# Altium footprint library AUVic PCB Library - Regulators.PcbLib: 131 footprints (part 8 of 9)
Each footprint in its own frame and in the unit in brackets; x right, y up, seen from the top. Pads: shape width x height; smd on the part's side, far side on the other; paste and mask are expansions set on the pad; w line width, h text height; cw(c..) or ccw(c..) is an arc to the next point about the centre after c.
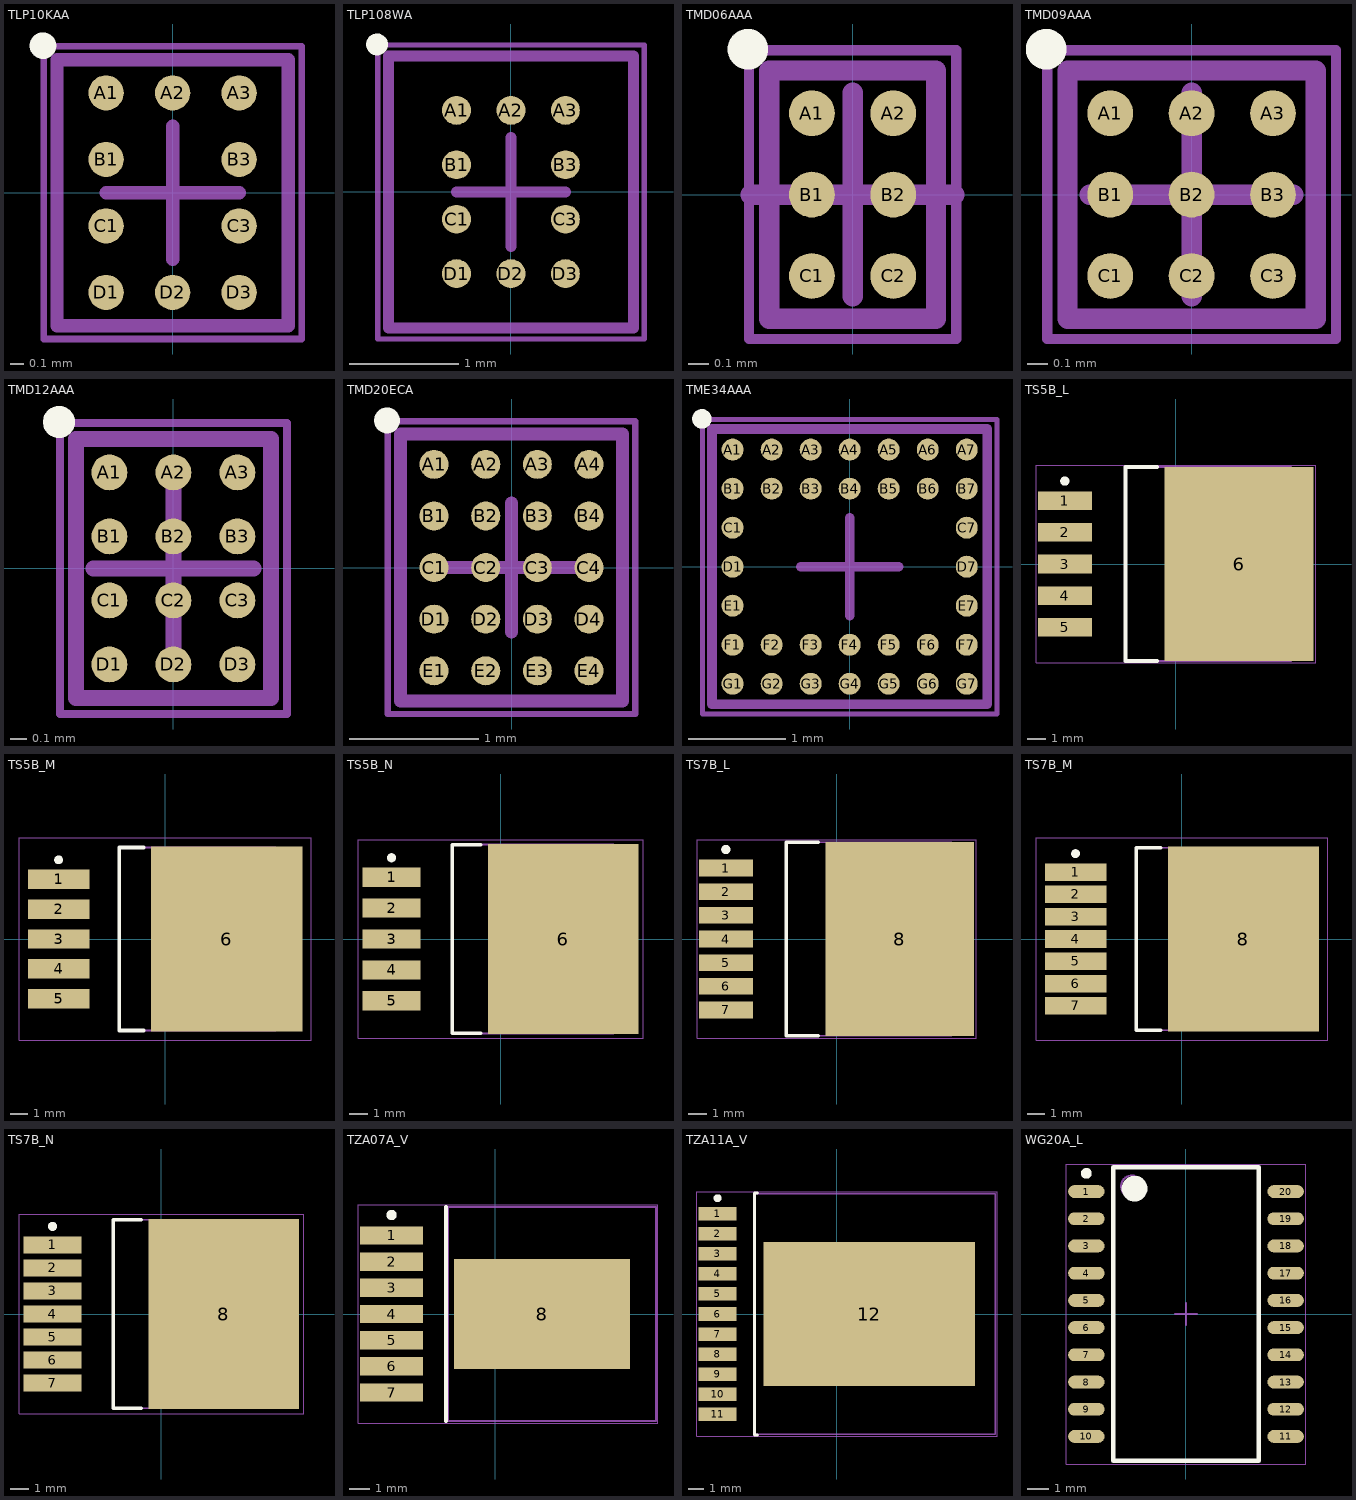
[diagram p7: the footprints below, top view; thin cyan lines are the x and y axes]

## TLP10KAA [mm] "Micro SMD, 10-Leads, Body 2x1.74mm, Pitch 0.5mm, NSC Recommended"
height 0.68
pads (10):
  round 0.265 smd paste-0.132 mask+0.05: A1(-0.5,0.75) A2(0,0.75) A3(0.5,0.75) B1(-0.5,0.25) B3(0.5,0.25) C1(-0.5,-0.25) C3(0.5,-0.25) D1(-0.5,-0.75) D2(0,-0.75) D3(0.5,-0.75)
Top Overlay:
  circle w0.1: c-0.975,1.105 r0.05
Top Paste:
  circle w0.05: c-0.575,0.675 r0.025
  circle w0.05: c-0.425,0.825 r0.025
  circle w0.05: c-0.425,0.675 r0.025
  circle w0.05: c-0.575,0.825 r0.025
  circle w0.05: c-0.075,0.675 r0.025
  circle w0.05: c0.075,0.825 r0.025
  circle w0.05: c0.075,0.675 r0.025
  circle w0.05: c-0.075,0.825 r0.025
  circle w0.05: c0.425,0.675 r0.025
  circle w0.05: c0.575,0.825 r0.025
  circle w0.05: c0.575,0.675 r0.025
  circle w0.05: c0.425,0.825 r0.025
  circle w0.05: c-0.575,0.175 r0.025
  circle w0.05: c-0.425,0.325 r0.025
  circle w0.05: c-0.425,0.175 r0.025
  circle w0.05: c-0.575,0.325 r0.025
  circle w0.05: c0.425,0.175 r0.025
  circle w0.05: c0.575,0.325 r0.025
  circle w0.05: c0.575,0.175 r0.025
  circle w0.05: c0.425,0.325 r0.025
  circle w0.05: c-0.575,-0.325 r0.025
  circle w0.05: c-0.425,-0.175 r0.025
  circle w0.05: c-0.425,-0.325 r0.025
  circle w0.05: c-0.575,-0.175 r0.025
  circle w0.05: c0.425,-0.325 r0.025
  circle w0.05: c0.575,-0.175 r0.025
  circle w0.05: c0.575,-0.325 r0.025
  circle w0.05: c0.425,-0.175 r0.025
  circle w0.05: c-0.575,-0.825 r0.025
  circle w0.05: c-0.425,-0.675 r0.025
  circle w0.05: c-0.425,-0.825 r0.025
  circle w0.05: c-0.575,-0.675 r0.025
  circle w0.05: c-0.075,-0.825 r0.025
  circle w0.05: c0.075,-0.675 r0.025
  circle w0.05: c0.075,-0.825 r0.025
  circle w0.05: c-0.075,-0.675 r0.025
  circle w0.05: c0.425,-0.825 r0.025
  circle w0.05: c0.575,-0.675 r0.025
  circle w0.05: c0.575,-0.825 r0.025
  circle w0.05: c0.425,-0.675 r0.025
  region: -0.575,0.825 -0.575,0.675 -0.425,0.675 -0.425,0.825
  region: -0.575,0.675 -0.575,0.825 -0.625,0.825 -0.625,0.675
  rectangle: -0.575,0.825 -0.425,0.875
  region: -0.425,0.825 -0.425,0.675 -0.375,0.675 -0.375,0.825
  region: -0.425,0.675 -0.575,0.675 -0.575,0.625 -0.425,0.625
  region: -0.075,0.825 -0.075,0.675 0.075,0.675 0.075,0.825
  region: -0.075,0.675 -0.075,0.825 -0.125,0.825 -0.125,0.675
  rectangle: -0.075,0.825 0.075,0.875
  region: 0.075,0.825 0.075,0.675 0.125,0.675 0.125,0.825
  region: 0.075,0.675 -0.075,0.675 -0.075,0.625 0.075,0.625
  region: 0.425,0.825 0.425,0.675 0.575,0.675 0.575,0.825
  region: 0.425,0.675 0.425,0.825 0.375,0.825 0.375,0.675
  rectangle: 0.425,0.825 0.575,0.875
  region: 0.575,0.825 0.575,0.675 0.625,0.675 0.625,0.825
  region: 0.575,0.675 0.425,0.675 0.425,0.625 0.575,0.625
  region: -0.575,0.325 -0.575,0.175 -0.425,0.175 -0.425,0.325
  region: -0.575,0.175 -0.575,0.325 -0.625,0.325 -0.625,0.175
  rectangle: -0.575,0.325 -0.425,0.375
  region: -0.425,0.325 -0.425,0.175 -0.375,0.175 -0.375,0.325
  region: -0.425,0.175 -0.575,0.175 -0.575,0.125 -0.425,0.125
  region: 0.425,0.325 0.425,0.175 0.575,0.175 0.575,0.325
  region: 0.425,0.175 0.425,0.325 0.375,0.325 0.375,0.175
  rectangle: 0.425,0.325 0.575,0.375
  region: 0.575,0.325 0.575,0.175 0.625,0.175 0.625,0.325
  region: 0.575,0.175 0.425,0.175 0.425,0.125 0.575,0.125
  region: -0.575,-0.175 -0.575,-0.325 -0.425,-0.325 -0.425,-0.175
  region: -0.575,-0.325 -0.575,-0.175 -0.625,-0.175 -0.625,-0.325
  rectangle: -0.575,-0.175 -0.425,-0.125
  region: -0.425,-0.175 -0.425,-0.325 -0.375,-0.325 -0.375,-0.175
  region: -0.425,-0.325 -0.575,-0.325 -0.575,-0.375 -0.425,-0.375
  region: 0.425,-0.175 0.425,-0.325 0.575,-0.325 0.575,-0.175
  region: 0.425,-0.325 0.425,-0.175 0.375,-0.175 0.375,-0.325
  rectangle: 0.425,-0.175 0.575,-0.125
  region: 0.575,-0.175 0.575,-0.325 0.625,-0.325 0.625,-0.175
  region: 0.575,-0.325 0.425,-0.325 0.425,-0.375 0.575,-0.375
  region: -0.575,-0.675 -0.575,-0.825 -0.425,-0.825 -0.425,-0.675
  region: -0.575,-0.825 -0.575,-0.675 -0.625,-0.675 -0.625,-0.825
  rectangle: -0.575,-0.675 -0.425,-0.625
  region: -0.425,-0.675 -0.425,-0.825 -0.375,-0.825 -0.375,-0.675
  region: -0.425,-0.825 -0.575,-0.825 -0.575,-0.875 -0.425,-0.875
  region: -0.075,-0.675 -0.075,-0.825 0.075,-0.825 0.075,-0.675
  region: -0.075,-0.825 -0.075,-0.675 -0.125,-0.675 -0.125,-0.825
  rectangle: -0.075,-0.675 0.075,-0.625
  region: 0.075,-0.675 0.075,-0.825 0.125,-0.825 0.125,-0.675
  region: 0.075,-0.825 -0.075,-0.825 -0.075,-0.875 0.075,-0.875
  region: 0.425,-0.675 0.425,-0.825 0.575,-0.825 0.575,-0.675
  region: 0.425,-0.825 0.425,-0.675 0.375,-0.675 0.375,-0.825
  rectangle: 0.425,-0.675 0.575,-0.625
  region: 0.575,-0.675 0.575,-0.825 0.625,-0.825 0.625,-0.675
  region: 0.575,-0.825 0.425,-0.825 0.425,-0.875 0.575,-0.875
Mechanical 13:
  lines w0.1: -0.87,-1 -0.87,1 0.87,1 0.87,-1 -0.87,-1
Mechanical 15:
  lines w0.05: -0.97,-1.1 -0.97,1.1 0.97,1.1 0.97,-1.1 -0.97,-1.1
  lines w0.1: -0.5,0 0.5,0 ; 0,-0.5 0,0.5
3D body: height 0.68, standoff 0, extent -0.87,-1 0.87,1

## TLP108WA [mm] "Micro SMD, 10-Leads, Body 2.5x2.25mm, Pitch 0.5mm, NSC Recommended"
height 0.68
pads (10):
  round 0.265 smd paste-0.132 mask+0.05: A1(-0.5,0.75) A2(0,0.75) A3(0.5,0.75) B1(-0.5,0.25) B3(0.5,0.25) C1(-0.5,-0.25) C3(0.5,-0.25) D1(-0.5,-0.75) D2(0,-0.75) D3(0.5,-0.75)
Top Overlay:
  circle w0.1: c-1.23,1.355 r0.05
Top Paste:
  circle w0.05: c-0.575,0.675 r0.025
  circle w0.05: c-0.425,0.825 r0.025
  circle w0.05: c-0.425,0.675 r0.025
  circle w0.05: c-0.575,0.825 r0.025
  circle w0.05: c-0.075,0.675 r0.025
  circle w0.05: c0.075,0.825 r0.025
  circle w0.05: c0.075,0.675 r0.025
  circle w0.05: c-0.075,0.825 r0.025
  circle w0.05: c0.425,0.675 r0.025
  circle w0.05: c0.575,0.825 r0.025
  circle w0.05: c0.575,0.675 r0.025
  circle w0.05: c0.425,0.825 r0.025
  circle w0.05: c-0.575,0.175 r0.025
  circle w0.05: c-0.425,0.325 r0.025
  circle w0.05: c-0.425,0.175 r0.025
  circle w0.05: c-0.575,0.325 r0.025
  circle w0.05: c0.425,0.175 r0.025
  circle w0.05: c0.575,0.325 r0.025
  circle w0.05: c0.575,0.175 r0.025
  circle w0.05: c0.425,0.325 r0.025
  circle w0.05: c-0.575,-0.325 r0.025
  circle w0.05: c-0.425,-0.175 r0.025
  circle w0.05: c-0.425,-0.325 r0.025
  circle w0.05: c-0.575,-0.175 r0.025
  circle w0.05: c0.425,-0.325 r0.025
  circle w0.05: c0.575,-0.175 r0.025
  circle w0.05: c0.575,-0.325 r0.025
  circle w0.05: c0.425,-0.175 r0.025
  circle w0.05: c-0.575,-0.825 r0.025
  circle w0.05: c-0.425,-0.675 r0.025
  circle w0.05: c-0.425,-0.825 r0.025
  circle w0.05: c-0.575,-0.675 r0.025
  circle w0.05: c-0.075,-0.825 r0.025
  circle w0.05: c0.075,-0.675 r0.025
  circle w0.05: c0.075,-0.825 r0.025
  circle w0.05: c-0.075,-0.675 r0.025
  circle w0.05: c0.425,-0.825 r0.025
  circle w0.05: c0.575,-0.675 r0.025
  circle w0.05: c0.575,-0.825 r0.025
  circle w0.05: c0.425,-0.675 r0.025
  region: -0.575,0.825 -0.575,0.675 -0.425,0.675 -0.425,0.825
  region: -0.575,0.675 -0.575,0.825 -0.625,0.825 -0.625,0.675
  rectangle: -0.575,0.825 -0.425,0.875
  region: -0.425,0.825 -0.425,0.675 -0.375,0.675 -0.375,0.825
  region: -0.425,0.675 -0.575,0.675 -0.575,0.625 -0.425,0.625
  region: -0.075,0.825 -0.075,0.675 0.075,0.675 0.075,0.825
  region: -0.075,0.675 -0.075,0.825 -0.125,0.825 -0.125,0.675
  rectangle: -0.075,0.825 0.075,0.875
  region: 0.075,0.825 0.075,0.675 0.125,0.675 0.125,0.825
  region: 0.075,0.675 -0.075,0.675 -0.075,0.625 0.075,0.625
  region: 0.425,0.825 0.425,0.675 0.575,0.675 0.575,0.825
  region: 0.425,0.675 0.425,0.825 0.375,0.825 0.375,0.675
  rectangle: 0.425,0.825 0.575,0.875
  region: 0.575,0.825 0.575,0.675 0.625,0.675 0.625,0.825
  region: 0.575,0.675 0.425,0.675 0.425,0.625 0.575,0.625
  region: -0.575,0.325 -0.575,0.175 -0.425,0.175 -0.425,0.325
  region: -0.575,0.175 -0.575,0.325 -0.625,0.325 -0.625,0.175
  rectangle: -0.575,0.325 -0.425,0.375
  region: -0.425,0.325 -0.425,0.175 -0.375,0.175 -0.375,0.325
  region: -0.425,0.175 -0.575,0.175 -0.575,0.125 -0.425,0.125
  region: 0.425,0.325 0.425,0.175 0.575,0.175 0.575,0.325
  region: 0.425,0.175 0.425,0.325 0.375,0.325 0.375,0.175
  rectangle: 0.425,0.325 0.575,0.375
  region: 0.575,0.325 0.575,0.175 0.625,0.175 0.625,0.325
  region: 0.575,0.175 0.425,0.175 0.425,0.125 0.575,0.125
  region: -0.575,-0.175 -0.575,-0.325 -0.425,-0.325 -0.425,-0.175
  region: -0.575,-0.325 -0.575,-0.175 -0.625,-0.175 -0.625,-0.325
  rectangle: -0.575,-0.175 -0.425,-0.125
  region: -0.425,-0.175 -0.425,-0.325 -0.375,-0.325 -0.375,-0.175
  region: -0.425,-0.325 -0.575,-0.325 -0.575,-0.375 -0.425,-0.375
  region: 0.425,-0.175 0.425,-0.325 0.575,-0.325 0.575,-0.175
  region: 0.425,-0.325 0.425,-0.175 0.375,-0.175 0.375,-0.325
  rectangle: 0.425,-0.175 0.575,-0.125
  region: 0.575,-0.175 0.575,-0.325 0.625,-0.325 0.625,-0.175
  region: 0.575,-0.325 0.425,-0.325 0.425,-0.375 0.575,-0.375
  region: -0.575,-0.675 -0.575,-0.825 -0.425,-0.825 -0.425,-0.675
  region: -0.575,-0.825 -0.575,-0.675 -0.625,-0.675 -0.625,-0.825
  rectangle: -0.575,-0.675 -0.425,-0.625
  region: -0.425,-0.675 -0.425,-0.825 -0.375,-0.825 -0.375,-0.675
  region: -0.425,-0.825 -0.575,-0.825 -0.575,-0.875 -0.425,-0.875
  region: -0.075,-0.675 -0.075,-0.825 0.075,-0.825 0.075,-0.675
  region: -0.075,-0.825 -0.075,-0.675 -0.125,-0.675 -0.125,-0.825
  rectangle: -0.075,-0.675 0.075,-0.625
  region: 0.075,-0.675 0.075,-0.825 0.125,-0.825 0.125,-0.675
  region: 0.075,-0.825 -0.075,-0.825 -0.075,-0.875 0.075,-0.875
  region: 0.425,-0.675 0.425,-0.825 0.575,-0.825 0.575,-0.675
  region: 0.425,-0.825 0.425,-0.675 0.375,-0.675 0.375,-0.825
  rectangle: 0.425,-0.675 0.575,-0.625
  region: 0.575,-0.675 0.575,-0.825 0.625,-0.825 0.625,-0.675
  region: 0.575,-0.825 0.425,-0.825 0.425,-0.875 0.575,-0.875
Mechanical 13:
  lines w0.1: -1.125,-1.25 -1.125,1.25 1.125,1.25 1.125,-1.25 -1.125,-1.25
Mechanical 15:
  lines w0.05: -1.225,-1.35 -1.225,1.35 1.225,1.35 1.225,-1.35 -1.225,-1.35
  lines w0.1: -0.5,0 0.5,0 ; 0,-0.5 0,0.5
3D body: height 0.68, standoff 0, extent -1.125,-1.25 1.125,1.25

## TMD06AAA [mm] "Micro SMD, 6-Leads, Body 1.22x0.82mm, Pitch 0.4mm, NSC Recommended"
height 0.68
pads (6):
  round 0.225 smd paste-0.112 mask+0.05: A1(-0.2,0.4) A2(0.2,0.4) B1(-0.2,0) B2(0.2,0) C1(-0.2,-0.4) C2(0.2,-0.4)
Top Overlay:
  circle w0.1: c-0.515,0.715 r0.05
Top Paste:
  circle w0.05: c0.275,-0.475 r0.025
  circle w0.05: c0.125,-0.325 r0.025
  circle w0.05: c0.125,-0.475 r0.025
  circle w0.05: c0.275,-0.325 r0.025
  circle w0.05: c-0.125,-0.475 r0.025
  circle w0.05: c-0.275,-0.325 r0.025
  circle w0.05: c-0.275,-0.475 r0.025
  circle w0.05: c-0.125,-0.325 r0.025
  circle w0.05: c0.275,-0.075 r0.025
  circle w0.05: c0.125,0.075 r0.025
  circle w0.05: c0.125,-0.075 r0.025
  circle w0.05: c0.275,0.075 r0.025
  circle w0.05: c-0.125,-0.075 r0.025
  circle w0.05: c-0.275,0.075 r0.025
  circle w0.05: c-0.275,-0.075 r0.025
  circle w0.05: c-0.125,0.075 r0.025
  circle w0.05: c0.275,0.325 r0.025
  circle w0.05: c0.125,0.475 r0.025
  circle w0.05: c0.125,0.325 r0.025
  circle w0.05: c0.275,0.475 r0.025
  circle w0.05: c-0.125,0.325 r0.025
  circle w0.05: c-0.275,0.475 r0.025
  circle w0.05: c-0.275,0.325 r0.025
  circle w0.05: c-0.125,0.475 r0.025
  region: 0.125,-0.325 0.125,-0.475 0.275,-0.475 0.275,-0.325
  region: 0.325,-0.475 0.325,-0.325 0.275,-0.325 0.275,-0.475
  region: 0.275,-0.275 0.125,-0.275 0.125,-0.325 0.275,-0.325
  region: 0.075,-0.325 0.075,-0.475 0.125,-0.475 0.125,-0.325
  rectangle: 0.125,-0.525 0.275,-0.475
  region: -0.275,-0.325 -0.275,-0.475 -0.125,-0.475 -0.125,-0.325
  region: -0.075,-0.475 -0.075,-0.325 -0.125,-0.325 -0.125,-0.475
  region: -0.125,-0.275 -0.275,-0.275 -0.275,-0.325 -0.125,-0.325
  region: -0.325,-0.325 -0.325,-0.475 -0.275,-0.475 -0.275,-0.325
  rectangle: -0.275,-0.525 -0.125,-0.475
  region: 0.125,0.075 0.125,-0.075 0.275,-0.075 0.275,0.075
  region: 0.325,-0.075 0.325,0.075 0.275,0.075 0.275,-0.075
  region: 0.275,0.125 0.125,0.125 0.125,0.075 0.275,0.075
  region: 0.075,0.075 0.075,-0.075 0.125,-0.075 0.125,0.075
  rectangle: 0.125,-0.125 0.275,-0.075
  region: -0.275,0.075 -0.275,-0.075 -0.125,-0.075 -0.125,0.075
  region: -0.075,-0.075 -0.075,0.075 -0.125,0.075 -0.125,-0.075
  region: -0.125,0.125 -0.275,0.125 -0.275,0.075 -0.125,0.075
  region: -0.325,0.075 -0.325,-0.075 -0.275,-0.075 -0.275,0.075
  rectangle: -0.275,-0.125 -0.125,-0.075
  region: 0.125,0.475 0.125,0.325 0.275,0.325 0.275,0.475
  region: 0.325,0.325 0.325,0.475 0.275,0.475 0.275,0.325
  region: 0.275,0.525 0.125,0.525 0.125,0.475 0.275,0.475
  region: 0.075,0.475 0.075,0.325 0.125,0.325 0.125,0.475
  rectangle: 0.125,0.275 0.275,0.325
  region: -0.275,0.475 -0.275,0.325 -0.125,0.325 -0.125,0.475
  region: -0.075,0.325 -0.075,0.475 -0.125,0.475 -0.125,0.325
  region: -0.125,0.525 -0.275,0.525 -0.275,0.475 -0.125,0.475
  region: -0.325,0.475 -0.325,0.325 -0.275,0.325 -0.275,0.475
  rectangle: -0.275,0.275 -0.125,0.325
Mechanical 13:
  lines w0.1: -0.41,-0.61 0.41,-0.61 0.41,0.61 -0.41,0.61 -0.41,-0.61
Mechanical 15:
  lines w0.05: -0.51,-0.71 0.51,-0.71 0.51,0.71 -0.51,0.71 -0.51,-0.71
  lines w0.1: -0.5,0 0.5,0 ; 0,-0.5 0,0.5
3D body: height 0.68, standoff 0, extent -0.41,-0.61 0.41,0.61

## TMD09AAA [mm] "Micro SMD, 9-Leads, Body 1.22x1.22mm, Pitch 0.4mm, NSC Recommended"
height 0.68
pads (9):
  round 0.225 smd paste-0.112 mask+0.05: A1(-0.4,0.4) A2(0,0.4) A3(0.4,0.4) B1(-0.4,0) B2(0,0) B3(0.4,0) C1(-0.4,-0.4) C2(0,-0.4) C3(0.4,-0.4)
Top Overlay:
  circle w0.1: c-0.715,0.715 r0.05
Top Paste:
  circle w0.05: c0.475,-0.475 r0.025
  circle w0.05: c0.325,-0.325 r0.025
  circle w0.05: c0.325,-0.475 r0.025
  circle w0.05: c0.475,-0.325 r0.025
  circle w0.05: c0.075,-0.475 r0.025
  circle w0.05: c-0.075,-0.325 r0.025
  circle w0.05: c-0.075,-0.475 r0.025
  circle w0.05: c0.075,-0.325 r0.025
  circle w0.05: c-0.325,-0.475 r0.025
  circle w0.05: c-0.475,-0.325 r0.025
  circle w0.05: c-0.475,-0.475 r0.025
  circle w0.05: c-0.325,-0.325 r0.025
  circle w0.05: c0.475,-0.075 r0.025
  circle w0.05: c0.325,0.075 r0.025
  circle w0.05: c0.325,-0.075 r0.025
  circle w0.05: c0.475,0.075 r0.025
  circle w0.05: c0.075,-0.075 r0.025
  circle w0.05: c-0.075,0.075 r0.025
  circle w0.05: c-0.075,-0.075 r0.025
  circle w0.05: c0.075,0.075 r0.025
  circle w0.05: c-0.325,-0.075 r0.025
  circle w0.05: c-0.475,0.075 r0.025
  circle w0.05: c-0.475,-0.075 r0.025
  circle w0.05: c-0.325,0.075 r0.025
  circle w0.05: c0.475,0.325 r0.025
  circle w0.05: c0.325,0.475 r0.025
  circle w0.05: c0.325,0.325 r0.025
  circle w0.05: c0.475,0.475 r0.025
  circle w0.05: c0.075,0.325 r0.025
  circle w0.05: c-0.075,0.475 r0.025
  circle w0.05: c-0.075,0.325 r0.025
  circle w0.05: c0.075,0.475 r0.025
  circle w0.05: c-0.325,0.325 r0.025
  circle w0.05: c-0.475,0.475 r0.025
  circle w0.05: c-0.475,0.325 r0.025
  circle w0.05: c-0.325,0.475 r0.025
  region: 0.325,-0.325 0.325,-0.475 0.475,-0.475 0.475,-0.325
  region: 0.525,-0.475 0.525,-0.325 0.475,-0.325 0.475,-0.475
  region: 0.475,-0.275 0.325,-0.275 0.325,-0.325 0.475,-0.325
  region: 0.275,-0.325 0.275,-0.475 0.325,-0.475 0.325,-0.325
  rectangle: 0.325,-0.525 0.475,-0.475
  region: -0.075,-0.325 -0.075,-0.475 0.075,-0.475 0.075,-0.325
  region: 0.125,-0.475 0.125,-0.325 0.075,-0.325 0.075,-0.475
  region: 0.075,-0.275 -0.075,-0.275 -0.075,-0.325 0.075,-0.325
  region: -0.125,-0.325 -0.125,-0.475 -0.075,-0.475 -0.075,-0.325
  rectangle: -0.075,-0.525 0.075,-0.475
  region: -0.475,-0.325 -0.475,-0.475 -0.325,-0.475 -0.325,-0.325
  region: -0.275,-0.475 -0.275,-0.325 -0.325,-0.325 -0.325,-0.475
  region: -0.325,-0.275 -0.475,-0.275 -0.475,-0.325 -0.325,-0.325
  region: -0.525,-0.325 -0.525,-0.475 -0.475,-0.475 -0.475,-0.325
  rectangle: -0.475,-0.525 -0.325,-0.475
  region: 0.325,0.075 0.325,-0.075 0.475,-0.075 0.475,0.075
  region: 0.525,-0.075 0.525,0.075 0.475,0.075 0.475,-0.075
  region: 0.475,0.125 0.325,0.125 0.325,0.075 0.475,0.075
  region: 0.275,0.075 0.275,-0.075 0.325,-0.075 0.325,0.075
  rectangle: 0.325,-0.125 0.475,-0.075
  region: -0.075,0.075 -0.075,-0.075 0.075,-0.075 0.075,0.075
  region: 0.125,-0.075 0.125,0.075 0.075,0.075 0.075,-0.075
  region: 0.075,0.125 -0.075,0.125 -0.075,0.075 0.075,0.075
  region: -0.125,0.075 -0.125,-0.075 -0.075,-0.075 -0.075,0.075
  rectangle: -0.075,-0.125 0.075,-0.075
  region: -0.475,0.075 -0.475,-0.075 -0.325,-0.075 -0.325,0.075
  region: -0.275,-0.075 -0.275,0.075 -0.325,0.075 -0.325,-0.075
  region: -0.325,0.125 -0.475,0.125 -0.475,0.075 -0.325,0.075
  region: -0.525,0.075 -0.525,-0.075 -0.475,-0.075 -0.475,0.075
  rectangle: -0.475,-0.125 -0.325,-0.075
  region: 0.325,0.475 0.325,0.325 0.475,0.325 0.475,0.475
  region: 0.525,0.325 0.525,0.475 0.475,0.475 0.475,0.325
  region: 0.475,0.525 0.325,0.525 0.325,0.475 0.475,0.475
  region: 0.275,0.475 0.275,0.325 0.325,0.325 0.325,0.475
  rectangle: 0.325,0.275 0.475,0.325
  region: -0.075,0.475 -0.075,0.325 0.075,0.325 0.075,0.475
  region: 0.125,0.325 0.125,0.475 0.075,0.475 0.075,0.325
  region: 0.075,0.525 -0.075,0.525 -0.075,0.475 0.075,0.475
  region: -0.125,0.475 -0.125,0.325 -0.075,0.325 -0.075,0.475
  rectangle: -0.075,0.275 0.075,0.325
  region: -0.475,0.475 -0.475,0.325 -0.325,0.325 -0.325,0.475
  region: -0.275,0.325 -0.275,0.475 -0.325,0.475 -0.325,0.325
  region: -0.325,0.525 -0.475,0.525 -0.475,0.475 -0.325,0.475
  region: -0.525,0.475 -0.525,0.325 -0.475,0.325 -0.475,0.475
  rectangle: -0.475,0.275 -0.325,0.325
Mechanical 13:
  lines w0.1: -0.61,-0.61 0.61,-0.61 0.61,0.61 -0.61,0.61 -0.61,-0.61
Mechanical 15:
  lines w0.05: -0.71,-0.71 0.71,-0.71 0.71,0.71 -0.71,0.71 -0.71,-0.71
  lines w0.1: -0.5,0 0.5,0 ; 0,-0.5 0,0.5
3D body: height 0.68, standoff 0, extent -0.61,-0.61 0.61,0.61

## TMD12AAA [mm] "Micro SMD, 12-Leads, Body 1.62x1.22mm, Pitch 0.4mm, NSC Recommended"
height 0.68
pads (12):
  round 0.225 smd paste-0.112 mask+0.05: A1(-0.4,0.6) A2(0,0.6) A3(0.4,0.6) B1(-0.4,0.2) B2(0,0.2) B3(0.4,0.2) C1(-0.4,-0.2) C2(0,-0.2) C3(0.4,-0.2) D1(-0.4,-0.6) D2(0,-0.6) D3(0.4,-0.6)
Top Overlay:
  circle w0.1: c-0.715,0.915 r0.05
Top Paste:
  circle w0.05: c0.475,-0.675 r0.025
  circle w0.05: c0.325,-0.525 r0.025
  circle w0.05: c0.325,-0.675 r0.025
  circle w0.05: c0.475,-0.525 r0.025
  circle w0.05: c0.075,-0.675 r0.025
  circle w0.05: c-0.075,-0.525 r0.025
  circle w0.05: c-0.075,-0.675 r0.025
  circle w0.05: c0.075,-0.525 r0.025
  circle w0.05: c-0.325,-0.675 r0.025
  circle w0.05: c-0.475,-0.525 r0.025
  circle w0.05: c-0.475,-0.675 r0.025
  circle w0.05: c-0.325,-0.525 r0.025
  circle w0.05: c0.475,-0.275 r0.025
  circle w0.05: c0.325,-0.125 r0.025
  circle w0.05: c0.325,-0.275 r0.025
  circle w0.05: c0.475,-0.125 r0.025
  circle w0.05: c0.075,-0.275 r0.025
  circle w0.05: c-0.075,-0.125 r0.025
  circle w0.05: c-0.075,-0.275 r0.025
  circle w0.05: c0.075,-0.125 r0.025
  circle w0.05: c-0.325,-0.275 r0.025
  circle w0.05: c-0.475,-0.125 r0.025
  circle w0.05: c-0.475,-0.275 r0.025
  circle w0.05: c-0.325,-0.125 r0.025
  circle w0.05: c0.475,0.125 r0.025
  circle w0.05: c0.325,0.275 r0.025
  circle w0.05: c0.325,0.125 r0.025
  circle w0.05: c0.475,0.275 r0.025
  circle w0.05: c0.075,0.125 r0.025
  circle w0.05: c-0.075,0.275 r0.025
  circle w0.05: c-0.075,0.125 r0.025
  circle w0.05: c0.075,0.275 r0.025
  circle w0.05: c-0.325,0.125 r0.025
  circle w0.05: c-0.475,0.275 r0.025
  circle w0.05: c-0.475,0.125 r0.025
  circle w0.05: c-0.325,0.275 r0.025
  circle w0.05: c0.475,0.525 r0.025
  circle w0.05: c0.325,0.675 r0.025
  circle w0.05: c0.325,0.525 r0.025
  circle w0.05: c0.475,0.675 r0.025
  circle w0.05: c0.075,0.525 r0.025
  circle w0.05: c-0.075,0.675 r0.025
  circle w0.05: c-0.075,0.525 r0.025
  circle w0.05: c0.075,0.675 r0.025
  circle w0.05: c-0.325,0.525 r0.025
  circle w0.05: c-0.475,0.675 r0.025
  circle w0.05: c-0.475,0.525 r0.025
  circle w0.05: c-0.325,0.675 r0.025
  region: 0.325,-0.525 0.325,-0.675 0.475,-0.675 0.475,-0.525
  region: 0.525,-0.675 0.525,-0.525 0.475,-0.525 0.475,-0.675
  region: 0.475,-0.475 0.325,-0.475 0.325,-0.525 0.475,-0.525
  region: 0.275,-0.525 0.275,-0.675 0.325,-0.675 0.325,-0.525
  rectangle: 0.325,-0.725 0.475,-0.675
  region: -0.075,-0.525 -0.075,-0.675 0.075,-0.675 0.075,-0.525
  region: 0.125,-0.675 0.125,-0.525 0.075,-0.525 0.075,-0.675
  region: 0.075,-0.475 -0.075,-0.475 -0.075,-0.525 0.075,-0.525
  region: -0.125,-0.525 -0.125,-0.675 -0.075,-0.675 -0.075,-0.525
  rectangle: -0.075,-0.725 0.075,-0.675
  region: -0.475,-0.525 -0.475,-0.675 -0.325,-0.675 -0.325,-0.525
  region: -0.275,-0.675 -0.275,-0.525 -0.325,-0.525 -0.325,-0.675
  region: -0.325,-0.475 -0.475,-0.475 -0.475,-0.525 -0.325,-0.525
  region: -0.525,-0.525 -0.525,-0.675 -0.475,-0.675 -0.475,-0.525
  rectangle: -0.475,-0.725 -0.325,-0.675
  region: 0.325,-0.125 0.325,-0.275 0.475,-0.275 0.475,-0.125
  region: 0.525,-0.275 0.525,-0.125 0.475,-0.125 0.475,-0.275
  region: 0.475,-0.075 0.325,-0.075 0.325,-0.125 0.475,-0.125
  region: 0.275,-0.125 0.275,-0.275 0.325,-0.275 0.325,-0.125
  rectangle: 0.325,-0.325 0.475,-0.275
  region: -0.075,-0.125 -0.075,-0.275 0.075,-0.275 0.075,-0.125
  region: 0.125,-0.275 0.125,-0.125 0.075,-0.125 0.075,-0.275
  region: 0.075,-0.075 -0.075,-0.075 -0.075,-0.125 0.075,-0.125
  region: -0.125,-0.125 -0.125,-0.275 -0.075,-0.275 -0.075,-0.125
  rectangle: -0.075,-0.325 0.075,-0.275
  region: -0.475,-0.125 -0.475,-0.275 -0.325,-0.275 -0.325,-0.125
  region: -0.275,-0.275 -0.275,-0.125 -0.325,-0.125 -0.325,-0.275
  region: -0.325,-0.075 -0.475,-0.075 -0.475,-0.125 -0.325,-0.125
  region: -0.525,-0.125 -0.525,-0.275 -0.475,-0.275 -0.475,-0.125
  rectangle: -0.475,-0.325 -0.325,-0.275
  region: 0.325,0.275 0.325,0.125 0.475,0.125 0.475,0.275
  region: 0.525,0.125 0.525,0.275 0.475,0.275 0.475,0.125
  region: 0.475,0.325 0.325,0.325 0.325,0.275 0.475,0.275
  region: 0.275,0.275 0.275,0.125 0.325,0.125 0.325,0.275
  rectangle: 0.325,0.075 0.475,0.125
  region: -0.075,0.275 -0.075,0.125 0.075,0.125 0.075,0.275
  region: 0.125,0.125 0.125,0.275 0.075,0.275 0.075,0.125
  region: 0.075,0.325 -0.075,0.325 -0.075,0.275 0.075,0.275
  region: -0.125,0.275 -0.125,0.125 -0.075,0.125 -0.075,0.275
  rectangle: -0.075,0.075 0.075,0.125
  region: -0.475,0.275 -0.475,0.125 -0.325,0.125 -0.325,0.275
  region: -0.275,0.125 -0.275,0.275 -0.325,0.275 -0.325,0.125
  region: -0.325,0.325 -0.475,0.325 -0.475,0.275 -0.325,0.275
  region: -0.525,0.275 -0.525,0.125 -0.475,0.125 -0.475,0.275
  rectangle: -0.475,0.075 -0.325,0.125
  region: 0.325,0.675 0.325,0.525 0.475,0.525 0.475,0.675
  region: 0.525,0.525 0.525,0.675 0.475,0.675 0.475,0.525
  region: 0.475,0.725 0.325,0.725 0.325,0.675 0.475,0.675
  region: 0.275,0.675 0.275,0.525 0.325,0.525 0.325,0.675
  rectangle: 0.325,0.475 0.475,0.525
  region: -0.075,0.675 -0.075,0.525 0.075,0.525 0.075,0.675
  region: 0.125,0.525 0.125,0.675 0.075,0.675 0.075,0.525
  region: 0.075,0.725 -0.075,0.725 -0.075,0.675 0.075,0.675
  region: -0.125,0.675 -0.125,0.525 -0.075,0.525 -0.075,0.675
  rectangle: -0.075,0.475 0.075,0.525
  region: -0.475,0.675 -0.475,0.525 -0.325,0.525 -0.325,0.675
  region: -0.275,0.525 -0.275,0.675 -0.325,0.675 -0.325,0.525
  region: -0.325,0.725 -0.475,0.725 -0.475,0.675 -0.325,0.675
  region: -0.525,0.675 -0.525,0.525 -0.475,0.525 -0.475,0.675
  rectangle: -0.475,0.475 -0.325,0.525
Mechanical 13:
  lines w0.1: -0.61,-0.81 0.61,-0.81 0.61,0.81 -0.61,0.81 -0.61,-0.81
Mechanical 15:
  lines w0.05: -0.71,-0.91 0.71,-0.91 0.71,0.91 -0.71,0.91 -0.71,-0.91
  lines w0.1: -0.5,0 0.5,0 ; 0,-0.5 0,0.5
3D body: height 0.68, standoff 0, extent -0.61,-0.81 0.61,0.81

## TMD20ECA [mm] "Micro SMD, 20-Leads, Body 2.07x1.72mm, Pitch 0.4mm, NSC Recommended"
height 0.68
pads (20):
  round 0.225 smd paste-0.112 mask+0.05: A1(-0.6,0.8) A2(-0.2,0.8) A3(0.2,0.8) A4(0.6,0.8) B1(-0.6,0.4) B2(-0.2,0.4) B3(0.2,0.4) B4(0.6,0.4) C1(-0.6,0) C2(-0.2,0) C3(0.2,0) C4(0.6,0) D1(-0.6,-0.4) D2(-0.2,-0.4) D3(0.2,-0.4) D4(0.6,-0.4) E1(-0.6,-0.8) E2(-0.2,-0.8) E3(0.2,-0.8) E4(0.6,-0.8)
Top Overlay:
  circle w0.1: c-0.965,1.14 r0.05
Top Paste:
  drawing of 180 lines, arcs and shapes, not listed
Mechanical 13:
  lines w0.1: -0.86,-1.035 -0.86,1.035 0.86,1.035 0.86,-1.035 -0.86,-1.035
Mechanical 15:
  lines w0.05: -0.96,-1.135 -0.96,1.135 0.96,1.135 0.96,-1.135 -0.96,-1.135
  lines w0.1: -0.5,0 0.5,0 ; 0,-0.5 0,0.5
3D body: height 0.68, standoff 0, extent -0.86,-1.035 0.86,1.035

## TME34AAA [mm] "Micro SMD, 34-Leads, Body 2.82x2.82mm, Pitch 0.4mm, NSC Recommended"
height 0.68
pads (34):
  round 0.225 smd paste-0.112 mask+0.05: A1(-1.2,1.2) A2(-0.8,1.2) A3(-0.4,1.2) A4(0,1.2) A5(0.4,1.2) A6(0.8,1.2) A7(1.2,1.2) B1(-1.2,0.8) B2(-0.8,0.8) B3(-0.4,0.8) B4(0,0.8) B5(0.4,0.8) B6(0.8,0.8) B7(1.2,0.8) C1(-1.2,0.4) C7(1.2,0.4) D1(-1.2,0) D7(1.2,0) E1(-1.2,-0.4) E7(1.2,-0.4) F1(-1.2,-0.8) F2(-0.8,-0.8) F3(-0.4,-0.8) F4(0,-0.8) F5(0.4,-0.8) F6(0.8,-0.8) F7(1.2,-0.8) G1(-1.2,-1.2) G2(-0.8,-1.2) G3(-0.4,-1.2) G4(0,-1.2) G5(0.4,-1.2) G6(0.8,-1.2) G7(1.2,-1.2)
Top Overlay:
  circle w0.1: c-1.515,1.515 r0.05
Top Paste:
  drawing of 306 lines, arcs and shapes, not listed
Mechanical 13:
  lines w0.1: -1.41,-1.41 1.41,-1.41 1.41,1.41 -1.41,1.41 -1.41,-1.41
Mechanical 15:
  lines w0.05: -1.51,-1.51 1.51,-1.51 1.51,1.51 -1.51,1.51 -1.51,-1.51
  lines w0.1: -0.5,0 0.5,0 ; 0,-0.5 0,0.5

## TS5B_L [mm] "D2-PAK, 6-Leads, Body 8.6x10.2mm, Pitch 1.7mm, Lead Span 14.1mm, IPC High Density"
height 4.65
pads (6):
  rect 2.9x1 smd: 1(-5.95,3.4) 2(-5.95,1.7) 3(-5.95,0) 4(-5.95,-1.7) 5(-5.95,-3.4)
  rect 8x10.4 smd: 6(3.4,0)
Top Overlay:
  circle w0.25: c-5.95,4.45 r0.125
  lines w0.2: -1,-5.2 -2.7,-5.2 -2.7,5.2 -1,5.2
Mechanical 13:
  lines w0.1: -2.7,-5.2 -2.7,5.2 6.19,5.2 6.19,-5.2 -2.7,-5.2
Mechanical 15:
  lines w0.05: -7.5,-5.3 -7.5,5.3 7.5,5.3 7.5,-5.3 -7.5,-5.3
  lines w0.1: -0.5,0 0.5,0 ; 0,-0.5 0,0.5
3D body: height 4.65, standoff 0, extent -2.7,-5.2 6.19,5.2

## TS5B_M [mm] "D2-PAK, 6-Leads, Body 8.6x10.2mm, Pitch 1.7mm, Lead Span 14.1mm, IPC Low Density"
height 4.65
pads (6):
  rect 3.5x1.1 smd: 1(-6.05,3.4) 2(-6.05,1.7) 3(-6.05,0) 4(-6.05,-1.7) 5(-6.05,-3.4)
  rect 8.6x10.5 smd: 6(3.5,0)
Top Overlay:
  circle w0.25: c-6.05,4.5 r0.125
  lines w0.2: -1.2,-5.2 -2.6,-5.2 -2.6,5.2 -1.2,5.2
Mechanical 13:
  lines w0.1: -2.6,-5.2 6.29,-5.2 6.29,5.2 -2.6,5.2 -2.6,-5.2
Mechanical 15:
  lines w0.05: -8.3,-5.75 8.3,-5.75 8.3,5.75 -8.3,5.75 -8.3,-5.75
  lines w0.1: -0.5,0 0.5,0 ; 0,-0.5 0,0.5
3D body: height 4.65, standoff 0, extent -2.6,-5.2 6.29,5.2

## TS5B_N [mm] "D2-PAK, 6-Leads, Body 8.6x10.2mm, Pitch 1.7mm, Lead Span 14.1mm, IPC Medium Density"
height 4.65
pads (6):
  rect 3.2x1.05 smd: 1(-6,3.4) 2(-6,1.7) 3(-6,0) 4(-6,-1.7) 5(-6,-3.4)
  rect 8.3x10.45 smd: 6(3.45,0)
Top Overlay:
  circle w0.25: c-6,4.475 r0.125
  lines w0.2: -1.1,-5.2 -2.65,-5.2 -2.65,5.2 -1.1,5.2
Mechanical 13:
  lines w0.1: -2.65,-5.2 6.24,-5.2 6.24,5.2 -2.65,5.2 -2.65,-5.2
Mechanical 15:
  lines w0.05: -7.85,-5.475 7.85,-5.475 7.85,5.475 -7.85,5.475 -7.85,-5.475
  lines w0.1: -0.5,0 0.5,0 ; 0,-0.5 0,0.5
3D body: height 4.65, standoff 0, extent -2.65,-5.2 6.24,5.2

## TS7B_L [mm] "D2-PAK, 8-Leads, Body 8.6x10.2mm, Pitch 1.27mm, Lead Span 14.1mm, IPC High Density"
height 4.64
pads (8):
  rect 2.9x0.9 smd: 1(-5.95,3.81) 2(-5.95,2.54) 3(-5.95,1.27) 4(-5.95,0) 5(-5.95,-1.27) 6(-5.95,-2.54) 7(-5.95,-3.81)
  rect 8x10.45 smd: 8(3.4,0)
Top Overlay:
  circle w0.25: c-5.95,4.81 r0.125
  lines w0.2: -1,-5.2 -2.7,-5.2 -2.7,5.2 -1,5.2
Mechanical 13:
  lines w0.1: -2.7,-5.2 6.19,-5.2 6.19,5.2 -2.7,5.2 -2.7,-5.2
Mechanical 15:
  lines w0.05: -7.5,-5.325 7.5,-5.325 7.5,5.325 -7.5,5.325 -7.5,-5.325
  lines w0.1: -0.5,0 0.5,0 ; 0,-0.5 0,0.5
3D body: height 4.64, standoff 0, extent -2.7,-5.2 6.19,5.2

## TS7B_M [mm] "D2-PAK, 8-Leads, Body 8.6x10.2mm, Pitch 1.27mm, Lead Span 14.1mm, IPC Low Density"
height 4.64
pads (8):
  rect 3.5x1 smd: 1(-6.05,3.81) 2(-6.05,2.54) 3(-6.05,1.27) 4(-6.05,0) 5(-6.05,-1.27) 6(-6.05,-2.54) 7(-6.05,-3.81)
  rect 8.6x10.55 smd: 8(3.5,0)
Top Overlay:
  circle w0.25: c-6.05,4.86 r0.125
  lines w0.2: -1.2,-5.2 -2.6,-5.2 -2.6,5.2 -1.2,5.2
Mechanical 13:
  lines w0.1: -2.6,-5.2 -2.6,5.2 6.29,5.2 6.29,-5.2 -2.6,-5.2
Mechanical 15:
  lines w0.05: -8.3,-5.775 -8.3,5.775 8.3,5.775 8.3,-5.775 -8.3,-5.775
  lines w0.1: -0.5,0 0.5,0 ; 0,-0.5 0,0.5
3D body: height 4.64, standoff 0, extent -2.6,-5.2 6.29,5.2

## TS7B_N [mm] "D2-PAK, 8-Leads, Body 8.6x10.2mm, Pitch 1.27mm, Lead Span 14.1mm, IPC Medium Density"
height 4.64
pads (8):
  rect 3.2x0.95 smd: 1(-6,3.81) 2(-6,2.54) 3(-6,1.27) 4(-6,0) 5(-6,-1.27) 6(-6,-2.54) 7(-6,-3.81)
  rect 8.3x10.5 smd: 8(3.45,0)
Top Overlay:
  circle w0.25: c-6,4.835 r0.125
  lines w0.2: -1.1,-5.2 -2.65,-5.2 -2.65,5.2 -1.1,5.2
Mechanical 13:
  lines w0.1: -2.65,-5.2 6.24,-5.2 6.24,5.2 -2.65,5.2 -2.65,-5.2
Mechanical 15:
  lines w0.05: -7.85,-5.5 7.85,-5.5 7.85,5.5 -7.85,5.5 -7.85,-5.5
  lines w0.1: -0.5,0 0.5,0 ; 0,-0.5 0,0.5
3D body: height 4.64, standoff 0, extent -2.65,-5.2 6.24,5.2

## TZA07A_V [mm] "D2-PAK, 8-Leads, Body 9.9x10.2mm, Pitch 1.27mm, Lead Span 13.8mm, NSC Recommended"
height 4.67
pads (8):
  rect 3.06x0.89 smd: 1(-5.03,3.81) 2(-5.03,2.54) 3(-5.03,1.27) 4(-5.03,0) 5(-5.03,-1.27) 6(-5.03,-2.54) 7(-5.03,-3.81)
  rect 8.54x5.35 smd: 8(2.28,0)
Top Overlay:
  circle w0.25: c-5.03,4.805 r0.125
  lines w0.2: -2.39,-5.2 -2.39,5.2
Mechanical 13:
  lines w0.1: -2.3,-5.2 -2.3,5.2 7.801,5.2 7.801,-5.2 -2.3,-5.2
Mechanical 15:
  lines w0.05: -6.66,-5.3 -6.66,5.3 7.9,5.3 7.9,-5.3 -6.66,-5.3
  lines w0.1: -0.5,0 0.5,0 ; 0,-0.5 0,0.5
3D body: height 4.67, standoff 0, extent -2.3,-5.2 7.801,5.2

## TZA11A_V [mm] "TO, 12-Leads, Body 15x15mm, Pitch 1.27mm, Lead Span 17.8mm, NSC Recommended"
height 6
pads (12):
  rect 2.41x0.86 smd: 1(-7.54,6.35) 2(-7.54,5.08) 3(-7.54,3.81) 4(-7.54,2.54) 5(-7.54,1.27) 6(-7.54,0) 7(-7.54,-1.27) 8(-7.54,-2.54) 9(-7.54,-3.81) 10(-7.54,-5.08) 11(-7.54,-6.35)
  rect 13.37x9.126 smd: 12(2.06,0)
Top Overlay:
  circle w0.25: c-7.54,7.33 r0.125
  lines w0.2: -5.02,-7.65 -5.2,-7.65 -5.2,7.65 -5.02,7.65
Mechanical 13:
  lines w0.1: -5.2,-7.625 10.05,-7.625 10.05,7.625 -5.2,7.625 -5.2,-7.625
Mechanical 15:
  lines w0.05: -8.842,-7.725 10.148,-7.725 10.148,7.725 -8.842,7.725 -8.842,-7.725
  lines w0.1: -0.5,0 0.5,0 ; 0,-0.5 0,0.5
3D body: height 6, standoff 0, extent -5.2,-7.625 10.05,7.625

## WG20A_L [mm] "CERPACK, 20-Leads, Body 26.6x9.4mm, Pitch 1.27mm, IPC High Density"
height 2.5
pads (20):
  oval 1.7x0.6 smd: 1(-4.65,5.715) 2(-4.65,4.445) 3(-4.65,3.175) 4(-4.65,1.905) 5(-4.65,0.635) 6(-4.65,-0.635) 7(-4.65,-1.905) 8(-4.65,-3.175) 9(-4.65,-4.445) 10(-4.65,-5.715) 11(4.65,-5.715) 12(4.65,-4.445) 13(4.65,-3.175) 14(4.65,-1.905) 15(4.65,-0.635) 16(4.65,0.635) 17(4.65,1.905) 18(4.65,3.175) 19(4.65,4.445) 20(4.65,5.715)
Top Overlay:
  circle w0.25: c-4.65,6.565 r0.125
  circle w0.6: c-2.4,5.85 r0.3
  lines w0.2: -3.4,-6.85 -3.4,6.85 3.4,6.85 3.4,-6.85 -3.4,-6.85
Mechanical 13:
  circle w0.1: c-2.53,5.96 r0.5
  lines w0.1: -3.43,-6.86 -3.43,6.86 3.43,6.86 3.43,-6.86 -3.43,-6.86
Mechanical 15:
  lines w0.05: -5.6,-7 -5.6,7 5.6,7 5.6,-7 -5.6,-7
  lines w0.1: -0.5,0 0.5,0 ; 0,-0.5 0,0.5
3D body: height 2.5, standoff 0.1, extent -3.43,-6.86 3.43,6.86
